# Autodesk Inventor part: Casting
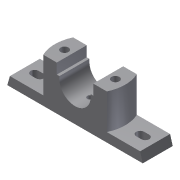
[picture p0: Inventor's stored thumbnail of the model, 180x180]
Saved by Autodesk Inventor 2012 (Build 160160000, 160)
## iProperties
Created: 2009-04
Part Number: Casting
Document SubType Name: Modeling
Designer: Sham
Density: 1 g/cm^3
Material: Default
Author: Sham
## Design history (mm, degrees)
sketch "Sketch1"
  geometry: L1 (-104, 0)-(104, 0); L2 (-104, 0)-(-100, 14); L3 (-100, 14)-(100, 14); L4 (100, 14)-(104, 0); 1 further point
  constraints: 8 end point, 1 horizontal, 1 midpoint, 1 parallel, 1 other
  dimensions: "d0" = 208 distance of L1.start L1.end; "d1" = 104 distance of L1.end point (0, 0); "d2" = 4 horizontal distance of L1.start L2.end; "d3" = 4 horizontal distance of L1.end L3.end; "d10" = 14 distance between parallel lines of L1 L3
extrude "Extrusion1" new body sketch "Sketch1" stored distance "d4" = 46; taper "d5" = 0 deg
sketch "Sketch2"
  geometry: L1 (51.143, 46)-(148.857, 46); L2 (148.857, 0)-(51.143, 0); A1 r 54 centre (100, 23) between (51.143, 46) and (51.143, 0); A2 r 54 centre (100, 23) between (148.857, 0) and (148.857, 46)
  constraints: 4 end point, 4 point on circle, 2 centre point, 1 parallel
extrude "Extrusion2" join sketch "Sketch2" distance "d8" = 54; taper "d9" = 0 deg
sketch "Sketch3"
  geometry: L1 (-28, 68)-(-28, 52); L2 (-28, 52)-(-24, 52); L3 (28, 68)-(28, 52); L4 (28, 52)-(24, 52); L5 (-28, 68)-(28, 68); L6 (-100, 14)-(-48.857, 14) reference; L7 (0, 48)-(0, 19); L8 (48.857, 14)-(100, 14) reference; L9 (48.857, 68)-(-48.857, 68) reference; L10 (-24, 48)-(-24, 52); L11 (24, 48)-(24, 52); A1 r 24 centre (0, 48) between (-24, 48) and (24, 48); 1 further point
  constraints: 16 end point, 5 perpendicular, 2 point on circle, 2 symmetric about line, 1 centre point, 1 tangent, 1 vertical alignment, 1 other
  dimensions: "d11" = 16 distance of L1.start L1.end; "d16" = 24 radius of A1; "d17" = 16 distance of L3.start L3.end; "d52" = 56 distance between parallel lines of L1 L3; "d54" = 54 distance between parallel lines of L8 L9 (derived)
extrude "Extrusion3" cut sketch "Sketch3" distance "d18" = 54; taper "d19" = 0 deg
sketch "Sketch4"
  geometry: L1 (-23, 29)-(-15, 29); L2 (-15, 17)-(-23, 17); L3 (-185, 29)-(-177, 29); L4 (-177, 17)-(-185, 17); A1 r 6 centre (-15, 23) between (-15, 17) and (-15, 29); A2 r 6 centre (-23, 23) between (-23, 29) and (-23, 17); A3 r 6 centre (-177, 23) between (-177, 17) and (-177, 29); A4 r 6 centre (-185, 23) between (-185, 29) and (-185, 17)
  constraints: 8 end point, 8 point on circle, 8 tangent, 4 centre point, 3 parallel
  dimensions: "d20" = 8 distance of A1.centre A2.centre; "d21" = 6 radius of A1; "d24" = 6 radius of A3; "d25" = 8 distance of A4.centre A3.centre
extrude "Extrusion4" cut sketch "Sketch4" distance "d28" = 54; taper "d29" = 0 deg
sketch "Sketch5"
  geometry: L1 (208, 0)-(0, 0) reference; L2 (52, -10)-(78, -10); L3 (78, -10)-(78, -36); L4 (78, -36)-(52, -36); L5 (52, -36)-(52, -10); L6 (130, -10)-(156, -10); L7 (156, -10)-(156, -36); L8 (156, -36)-(130, -36); L9 (130, -36)-(130, -10); L10 (0, -46)-(208, -46) reference; L11 (104, -23)-(104, -46)
  constraints: 18 end point, 5 perpendicular, 4 parallel, 2 horizontal, 1 midpoint
  dimensions: "d30" = 26 distance of L2.start L2.end; "d31" = 10 distance between parallel lines of L2 L1; "d32" = 10 distance between parallel lines of L1 L6; "d65" = 26 distance between parallel lines of L3 L11; "d66" = 26 distance between parallel lines of L9 L11
extrude "Extrusion5" cut sketch "Sketch5" distance "d34" = 10; taper "d35" = 0 deg
sketch "Sketch6"
  geometry: L1 (148.857, 0)-(128, 0) reference; L2 (72, 0)-(51.143, 0) reference; L3 (0, 46)-(0, 0) reference; L4 (200, 46)-(200, 0) reference; C1 r 6 at (61, 23); C2 r 6 at (139, 23); 1 further point
  constraints: 2 centre point, 1 equal radius
  dimensions: "d36" = 12 diameter of C1; "d37" = 78 distance of C2.centre C1.centre; "d39" = 39 distance of C2.centre point (100, 23); "d58" = 39 distance of C1.centre point (100, 23); "d59" = 23 distance from line of L1 C2.centre; "d60" = 23 distance from line of L2 C1.centre; "d61" = 61 distance from line of L3 C1.centre; "d62" = 61 distance from line of L4 C2.centre (derived)
extrude "Extrusion6" cut sketch "Sketch6" stored distance "d40" = 10; taper "d41" = 0 deg
workplane "Work Plane1"
sketch "Sketch7"
  geometry: L1 (-4, 46)-(204, 46) reference; L2 (-4, 0)-(-4, 46) reference; 1 further point
  dimensions: "d43" = 23 distance from line of L1 point (100, 23); "d44" = 104 distance from line of point (100, 23) L2
hole "Hole1" sketch "Sketch7" at (100, 23) diameter "d45" = 8; stored, may be unused: countersink angle "d49" = 90 deg, drill point angle "d51" = 118 deg; dims "d46" = 6, "d47" = 8, "d48" = 16, "d50" = 8
body "Solid1"
other parameters: "d6" = 108, "d42" = -52
